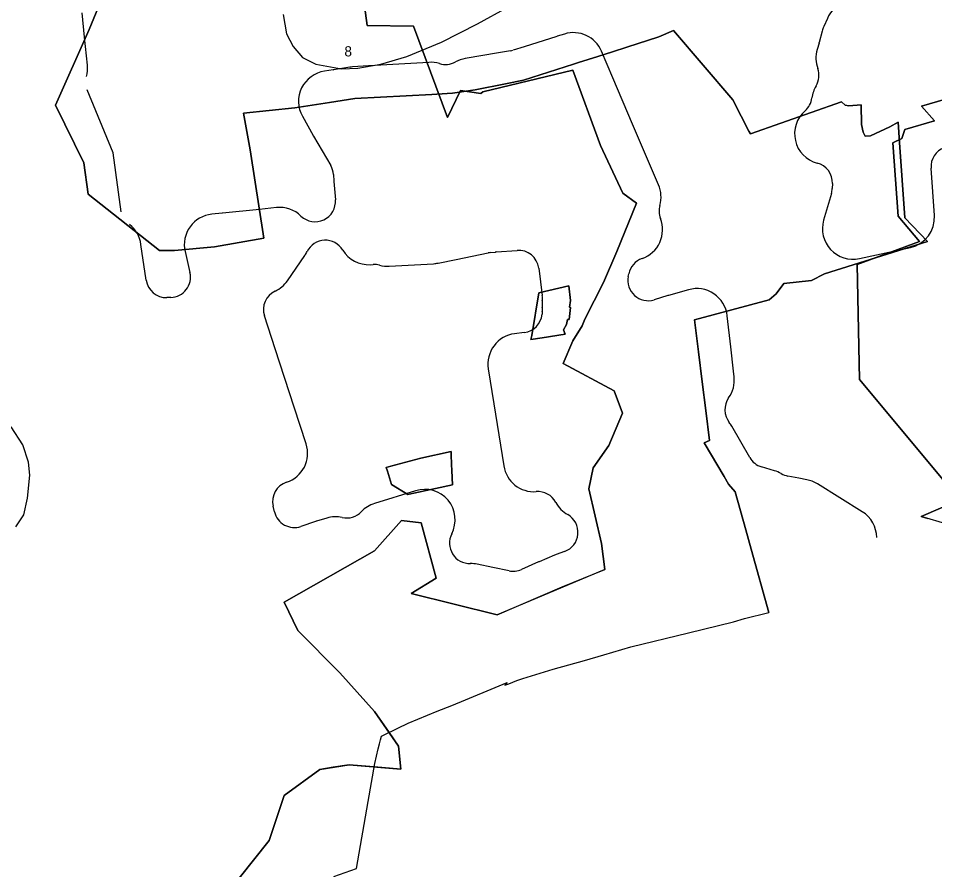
# Model space of a CAD drawing. Extents: x -445049 to -430649, y -1142304 to -1129816.
# Drawn here: x -443023 to -442122, y -1133134 to -1132297 of the extents above; entities that cross this region are included whole.
import ezdxf

# ---------------------------------------------------------------- set-up
doc = ezdxf.new("R2010")
doc.units = 0
for name, color, linetype in [('Vrstva 10', 7, 'Continuous'), ('Vrstva 23', 7, 'Continuous'), ('Vrstva 51', 7, 'Continuous'), ('Vrstva 7', 7, 'Continuous'), ('Vrstva 8', 7, 'Continuous'), ('Vrstva 9', 7, 'Continuous')]:
    doc.layers.add(name, color=color, linetype=linetype)

msp = doc.modelspace()

# ---------------------------------------------------------------- linework, layer by layer
at = {"layer": 'Vrstva 10'}
msp.add_lwpolyline([(-442109.03, -1132794.68), (-442135.55, -1132786.74), (-442097.52, -1132770.3), (-442196.18, -1132652.14), (-442198.38, -1132539.08), (-442137.12, -1132516.56), (-442158.19, -1132491.81), (-442163.27, -1132419.71), (-442154.54, -1132415.62), (-442151.59, -1132406.77), (-442122.25, -1132397.95), (-442135.23, -1132383.63), (-442097.99, -1132372.93)], dxfattribs=at)
at = {"layer": 'Vrstva 23'}
for p, q in [((-442957.74, -1132315.82), (-442960.18, -1132291.9)), ((-442227.66, -1132297.45), (-442231.2, -1132305.52)), ((-442232.75, -1132310.02), (-442235.63, -1132321.09)), ((-442954.94, -1132343.31), (-442957.74, -1132315.82)), ((-442493.43, -1132315.14), (-442525.56, -1132325.32)), ((-442486.1, -1132312.86), (-442493.26, -1132315.09)), ((-442235.8, -1132321.69), (-442237.68, -1132328.11)), ((-442539.18, -1132329.4), (-442550.89, -1132331.43)), ((-442525.63, -1132325.34), (-442536.62, -1132328.79)), ((-442438.41, -1132355.92), (-442449.62, -1132329.71)), ((-442551.01, -1132331.46), (-442583.52, -1132336.89)), ((-442713.29, -1132348.06), (-442721.83, -1132349.33)), ((-442696.97, -1132345.45), (-442713.06, -1132348.03)), ((-442678.78, -1132344.02), (-442694.4, -1132345.15)), ((-442619.3, -1132340.69), (-442678.28, -1132343.99)), ((-442419.09, -1132401.26), (-442438.4, -1132355.96)), ((-442743.65, -1132393.58), (-442733.12, -1132412.52)), ((-442393.54, -1132460.98), (-442419.08, -1132401.29)), ((-442732.79, -1132413.1), (-442715.81, -1132442.13)), ((-442122.5, -1132491.05), (-442125.76, -1132444.58)), ((-442713.13, -1132450.74), (-442712.63, -1132457.45)), ((-442712.62, -1132457.65), (-442711.15, -1132475.65)), ((-442222.69, -1132459.74), (-442222.89, -1132464.67)), ((-442223.67, -1132469.45), (-442231.32, -1132495.7)), ((-442768.9, -1132483.34), (-442785.65, -1132485.04)), ((-442822.34, -1132488.76), (-442832.71, -1132489.83)), ((-442785.65, -1132485.04), (-442822.28, -1132488.75)), ((-442897.11, -1132554.65), (-442902.23, -1132519.43)), ((-442858.87, -1132526.42), (-442854.12, -1132547)), ((-442592.49, -1132534.2), (-442560.97, -1132527.8)), ((-442559.04, -1132527.5), (-442553.72, -1132526.95)), ((-442553.15, -1132526.9), (-442532.68, -1132525.39)), ((-442196.12, -1132533.4), (-442146.02, -1132522.46)), ((-442758.36, -1132555.17), (-442741.27, -1132530.36)), ((-442741.27, -1132530.35), (-442741.17, -1132530.21)), ((-442610.33, -1132537.86), (-442592.53, -1132534.2)), ((-442676.81, -1132539.4), (-442674.08, -1132539.27)), ((-442658.19, -1132540.96), (-442614.62, -1132538.42)), ((-442511.38, -1132542.74), (-442507.85, -1132569.69)), ((-442423.3, -1132550.9), (-442422.8, -1132548.36)), ((-442364.18, -1132564.03), (-442383.92, -1132569.71)), ((-442872.96, -1132571.65), (-442876.71, -1132571.76)), ((-442384.3, -1132569.83), (-442397.89, -1132573.94)), ((-442770.36, -1132621.97), (-442780.93, -1132589.7)), ((-442507.87, -1132585.65), (-442508.11, -1132588.09)), ((-442322.63, -1132620.13), (-442326.06, -1132589.51)), ((-442525.49, -1132606.01), (-442535.04, -1132607.23)), ((-442751.63, -1132679.36), (-442770.35, -1132622)), ((-442319.97, -1132643.84), (-442322.63, -1132620.14)), ((-442560.87, -1132641.74), (-442555.38, -1132675.91)), ((-442319.32, -1132649.42), (-442319.96, -1132643.94)), ((-442739.92, -1132715.25), (-442751.62, -1132679.37)), ((-442555.37, -1132675.96), (-442550.51, -1132706.63)), ((-442304.03, -1132728.71), (-442321.53, -1132698.1)), ((-442550.51, -1132706.63), (-442545.69, -1132737.06)), ((-442279.61, -1132741.74), (-442292.35, -1132737.96)), ((-442255.77, -1132749.05), (-442266.65, -1132746.98)), ((-442247.76, -1132750.57), (-442255.77, -1132749.05)), ((-442632.38, -1132761.4), (-442672.71, -1132773.93)), ((-442193.37, -1132782.02), (-442237.52, -1132754.57)), ((-442771.06, -1132782.17), (-442772.36, -1132776.66)), ((-442719.65, -1132788.24), (-442729.71, -1132791.27)), ((-442730.73, -1132791.6), (-442745.14, -1132796.51)), ((-442495.73, -1132824.7), (-442511.06, -1132831.2)), ((-442485.94, -1132821.12), (-442494.19, -1132824.1)), ((-442556.5, -1132836.74), (-442571.71, -1132833.56)), ((-442511.41, -1132831.35), (-442528.41, -1132838.82)), ((-442540.54, -1132840.08), (-442556.5, -1132836.74))]:
    msp.add_line(p, q, dxfattribs=at)
msp.add_lwpolyline([(-442921.64, -1132487.44), (-442929.57, -1132429.68), (-442955.18, -1132367.68)], dxfattribs=at)
for centre, radius, start, end in [((-442200.18, -1132309.49), 30, 136.62933, 156.33647), ((-442477.2, -1132341.51), 30, 23.15168, 107.25965), ((-442203.72, -1132317.56), 30, 156.33647, 165.43444), ((-442937.84, -1132313.79), 20, 185.82227, 185.82544), ((-442484.36, -1132343.73), 30, 107.25965, 107.58988), ((-442254.99, -1132316.06), 20, 343.64627, 345.43444), ((-442542.6, -1132309.7), 20, 279.83922, 287.37641), ((-442531.6, -1132306.26), 20, 287.37641, 287.58988), ((-442208.89, -1132336.55), 30, 163.64627, 199.84662), ((-442578.57, -1132366.48), 30, 99.49232, 119.21234), ((-442554.31, -1132311.73), 20, 279.49232, 279.83922), ((-442984.78, -1132346.35), 30, 344.10309, 5.82544), ((-442716.22, -1132328.28), 20, 278.44397, 279.08948), ((-442692.23, -1132375.07), 30, 94.15381, 99.08948), ((-442676.61, -1132373.94), 30, 93.19748, 94.15381), ((-442617.62, -1132370.64), 30, 72.95959, 93.19748), ((-442602.97, -1132322.84), 20, 252.95959, 299.21234), ((-442255.92, -1132353.53), 20, 328.95738, 19.84662), ((-442717.43, -1132379), 30, 98.44397, 209.06864), ((-442466, -1132367.72), 30, 23.07993, 23.15168), ((-442212.78, -1132379.49), 30.35, 148.95738, 172.76176), ((-442262.73, -1132373.15), 20, 310.92226, 352.76176), ((-442230.13, -1132410.76), 29.77, 130.92226, 255.41229), ((-442400.69, -1132393.42), 20, 203.07993, 203.16557), ((-442706.9, -1132397.95), 30, 209.06864, 210.32596), ((-442105.81, -1132443.17), 20, 110.6205, 184.01796), ((-442191.84, -1132439.88), 50, 177.60823, 177.64508), ((-442733.08, -1132452.22), 20, 4.259, 30.32596), ((-442242.67, -1132458.92), 20, 357.64508, 75.41229), ((-442682.71, -1132455.22), 30, 184.25897, 184.65397), ((-442421.12, -1132472.78), 30, 343.82915, 23.16557), ((-442242.87, -1132463.85), 20, 343.74529, 357.64508), ((-442765.87, -1132513.19), 30, 45.9152, 95.7926), ((-442731.08, -1132477.27), 20, 225.9152, 4.65396), ((-442373.1, -1132486.71), 20, 163.82915, 201.5094), ((-442829.64, -1132519.67), 30, 95.88775, 192.9966), ((-442819.26, -1132518.6), 30, 95.78982, 95.88775), ((-442787.67, -1132465.14), 20, 275.78982, 275.7926), ((-442152.42, -1132493.15), 30, 282.32123, 4.01796), ((-442931.92, -1132523.75), 30, 8.27726, 52.36246), ((-442419.62, -1132505.04), 30, 289.19359, 21.5094), ((-442202.52, -1132504.09), 30, 163.74529, 282.32123), ((-442721.06, -1132535.36), 20, 31.22603, 153.67299), ((-442765.87, -1132513.19), 30, 325.43977, 333.67299), ((-442678.3, -1132509.44), 30, 211.22603, 272.84214), ((-442556.99, -1132547.4), 20, 95.88585, 101.47902), ((-442551.67, -1132546.85), 20, 94.23101, 95.88585), ((-442531.21, -1132545.33), 20, 7.46163, 94.23101), ((-442724.8, -1132541.7), 20, 145.43977, 145.44951), ((-442616.36, -1132508.47), 30, 273.3252, 281.61099), ((-442588.5, -1132553.8), 20, 101.47902, 101.61099), ((-442403.18, -1132552.26), 20, 109.19359, 168.76185), ((-442673.09, -1132559.24), 20, 74.74496, 92.84214), ((-442659.93, -1132511.01), 30, 254.74496, 273.3252), ((-442877.32, -1132551.77), 20, 188.27726, 271.74737), ((-442873.57, -1132551.66), 20, 271.74737, 13.18493), ((-442824.89, -1132540.25), 30, 192.9966, 193.18493), ((-442783.07, -1132538.16), 30, 295.00864, 325.44951), ((-442403.68, -1132554.8), 20, 168.76185, 286.83942), ((-442355.87, -1132592.85), 30, 6.39032, 106.07109), ((-442761.93, -1132583.47), 20, 115.00864, 198.13953), ((-442527.68, -1132572.29), 20, 353.04978, 7.46163), ((-442375.61, -1132598.54), 30, 106.07109, 106.83942), ((-442478.05, -1132578.34), 30, 173.04978, 186.09223), ((-442527.76, -1132583.64), 20, 354.25098, 6.09223), ((-442528.02, -1132586.17), 20, 277.27102, 354.34773), ((-442478.26, -1132591.09), 30, 174.25098, 174.34773), ((-442531.25, -1132636.98), 30, 97.27102, 189.13006), ((-442798.87, -1132631.31), 30, 18.08071, 18.13953), ((-442302.75, -1132617.91), 20, 186.39032, 186.3974), ((-442300.09, -1132641.61), 20, 186.3974, 186.6774), ((-442349.11, -1132652.91), 30, 324.52822, 6.6774), ((-442308.39, -1132681.93), 20, 144.52822, 218.41396), ((-442780.14, -1132688.67), 30, 18.05894, 18.08071), ((-442575.12, -1132679.08), 20, 8.99993, 9.13006), ((-442347.57, -1132712.99), 30, 29.76045, 38.41396), ((-442570.26, -1132709.76), 20, 8.99472, 8.99993), ((-442768.45, -1132724.55), 30, 288.12384, 18.05894), ((-442286.66, -1132718.79), 20, 209.75853, 253.49032), ((-442516.06, -1132732.37), 30, 188.99472, 274.36892), ((-442288.14, -1132770.5), 30, 59.69874, 73.49032), ((-442262.91, -1132727.33), 20, 239.69874, 259.22819), ((-442752.89, -1132772.07), 20, 108.12384, 193.25843), ((-442252.03, -1132729.4), 20, 259.22819, 259.2388), ((-442253.36, -1132780.04), 30, 58.12147, 79.2388), ((-442623.48, -1132790.05), 30, 332.75604, 107.25158), ((-442512.25, -1132782.22), 20, 27.9218, 94.36892), ((-442663.81, -1132802.58), 30, 107.25158, 136.50496), ((-442468.07, -1132758.81), 30, 207.9218, 240.46264), ((-442751.59, -1132777.58), 20, 193.25843, 288.82418), ((-442710.98, -1132816.96), 30, 77.4082, 106.78491), ((-442700.08, -1132768.16), 20, 257.4082, 316.50496), ((-442492.72, -1132802.31), 20, 289.82444, 60.46264), ((-442209.21, -1132807.5), 30, 0.15915, 58.12147), ((-442721.05, -1132820), 30, 106.78491, 108.82418), ((-442579.03, -1132812.94), 20, 152.75604, 271.35626), ((-442484.02, -1132852.32), 30, 109.82444, 112.97972), ((-442577.85, -1132862.93), 30, 78.18999, 91.35626), ((-442499.35, -1132858.82), 30, 112.97972, 113.70018), ((-442552.41, -1132817.17), 20, 258.18999, 258.19838), ((-442536.45, -1132820.5), 20, 258.19838, 293.70018)]:
    msp.add_arc(centre, radius, start, end, dxfattribs=at)
at = {"layer": 'Vrstva 51'}
for points in [[(-442762.66, -1132293.74), (-442759.13, -1132312.56), (-442752.64, -1132325), (-442743.57, -1132335.99), (-442730.45, -1132342.34), (-442705.24, -1132347.12), (-442689.1, -1132346.27), (-442666.56, -1132342.61), (-442640.85, -1132335.06), (-442606.79, -1132320.72), (-442571.63, -1132302.75), (-442541.55, -1132286.46)], [(-443025.22, -1132796.81), (-443017.38, -1132785.12), (-443013.68, -1132768.61), (-443011.59, -1132746.25), (-443012.68, -1132733.48), (-443018.34, -1132716.27), (-443029.71, -1132698.63)]]:
    msp.add_lwpolyline(points, dxfattribs=at)
at = {"layer": 'Vrstva 7'}
for points in [[(-442922.59, -1132233.93), (-442953.25, -1132308.47), (-442986.29, -1132382.77), (-442958.54, -1132439.22), (-442954.29, -1132470.17), (-442883.88, -1132525.49), (-442869.19, -1132525.36), (-442829.94, -1132521.75), (-442781.57, -1132513.28), (-442795.03, -1132426.67), (-442801.63, -1132390.42), (-442750.9, -1132385.4), (-442717.09, -1132380.1), (-442691.93, -1132376.15), (-442616.35, -1132372.16), (-442616.35, -1132372.16), (-442611.45, -1132371.9), (-442596.16, -1132371.1), (-442573.78, -1132367.82), (-442543.93, -1132361.77), (-442526.36, -1132358.21), (-442477.04, -1132342.43), (-442472.26, -1132340.9), (-442453.33, -1132334.85), (-442438.85, -1132330.22), (-442424.65, -1132325.68), (-442393.28, -1132315.65), (-442378.77, -1132309.31), (-442320.57, -1132377.44), (-442312.27, -1132393.66), (-442304.72, -1132408.4), (-442303.09, -1132411.01), (-442213.73, -1132379.55), (-442210.06, -1132382.66), (-442206.65, -1132383.46), (-442194.59, -1132382.53), (-442194.21, -1132401.61), (-442192.39, -1132409.19), (-442190.46, -1132413.21), (-442185.39, -1132412.76), (-442166.39, -1132404.06), (-442157.99, -1132399.36), (-442156.75, -1132419.42), (-442151.64, -1132493.29), (-442129.19, -1132516.78), (-442230.4, -1132548.48), (-442243.24, -1132554.95), (-442270.61, -1132557.94), (-442277.91, -1132567.95), (-442284.89, -1132573.96), (-442358.4, -1132593.69), (-442354.45, -1132625), (-442350.74, -1132654.35), (-442347.15, -1132682.73), (-442343.44, -1132712.19), (-442348.83, -1132714.24), (-442328.94, -1132747.55), (-442324.92, -1132754.94), (-442318.3, -1132762.38), (-442307.93, -1132799.8), (-442302.55, -1132818.91), (-442285.23, -1132881.09)], [(-442712.69, -1133140.21), (-442690.54, -1133132.6), (-442678.94, -1133066.74), (-442672.35, -1133029.29), (-442669.09, -1133015.08), (-442667.79, -1133010.13), (-442666.7, -1133005.99), (-442665.82, -1133002.63), (-442648.47, -1132994.02), (-442645.79, -1132992.69), (-442643.47, -1132991.54), (-442639.52, -1132989.58), (-442611.14, -1132977.99), (-442596.71, -1132972.33), (-442583.36, -1132966.7), (-442554.21, -1132954.62), (-442542.26, -1132949.89), (-442544.59, -1132952.4), (-442540.74, -1132951.01), (-442532.91, -1132947.79), (-442527.04, -1132945.99), (-442497.2, -1132936.83), (-442466.36, -1132928.28), (-442447.46, -1132922.71), (-442420.82, -1132914.86), (-442364.23, -1132900.95), (-442319.76, -1132890.16), (-442309.05, -1132886.83), (-442285.23, -1132881.09), (-442302.55, -1132818.91), (-442307.93, -1132799.8), (-442318.3, -1132762.38), (-442324.92, -1132754.94), (-442328.94, -1132747.55), (-442348.83, -1132714.24), (-442343.44, -1132712.19), (-442347.15, -1132682.73), (-442350.74, -1132654.35), (-442354.45, -1132625), (-442358.4, -1132593.69), (-442284.89, -1132573.96), (-442277.91, -1132567.95), (-442270.61, -1132557.94), (-442243.24, -1132554.95), (-442230.4, -1132548.48), (-442129.19, -1132516.78), (-442151.64, -1132493.29), (-442156.75, -1132419.42), (-442157.99, -1132399.36), (-442166.39, -1132404.06), (-442185.39, -1132412.76), (-442190.46, -1132413.21), (-442192.39, -1132409.19), (-442194.21, -1132401.61), (-442194.59, -1132382.53), (-442206.65, -1132383.46), (-442210.06, -1132382.66), (-442213.73, -1132379.55), (-442303.09, -1132411.01), (-442304.72, -1132408.4), (-442312.27, -1132393.66), (-442320.57, -1132377.44), (-442378.77, -1132309.31), (-442393.28, -1132315.65), (-442424.65, -1132325.68), (-442438.85, -1132330.22), (-442453.33, -1132334.85), (-442472.26, -1132340.9), (-442477.04, -1132342.43), (-442526.36, -1132358.21), (-442543.93, -1132361.77), (-442573.78, -1132367.82), (-442596.16, -1132371.1), (-442611.45, -1132371.9), (-442616.35, -1132372.16), (-442691.93, -1132376.15), (-442717.09, -1132380.1), (-442750.9, -1132385.4), (-442801.63, -1132390.42), (-442795.03, -1132426.67), (-442781.57, -1132513.28), (-442829.94, -1132521.75), (-442869.19, -1132525.36), (-442883.88, -1132525.49), (-442954.29, -1132470.17), (-442958.54, -1132439.22), (-442986.29, -1132382.77), (-442953.25, -1132308.47), (-442922.59, -1132233.93)], [(-442712.69, -1133140.21), (-442690.54, -1133132.6), (-442678.94, -1133066.74), (-442672.35, -1133029.29), (-442669.09, -1133015.08), (-442667.79, -1133010.13), (-442666.7, -1133005.99), (-442665.82, -1133002.63), (-442648.47, -1132994.02), (-442645.79, -1132992.69), (-442643.47, -1132991.54), (-442639.52, -1132989.58), (-442611.14, -1132977.99), (-442596.71, -1132972.33), (-442583.36, -1132966.7), (-442554.21, -1132954.62), (-442542.26, -1132949.89), (-442544.59, -1132952.4), (-442540.74, -1132951.01), (-442532.91, -1132947.79), (-442527.04, -1132945.99), (-442497.2, -1132936.83), (-442466.36, -1132928.28), (-442447.46, -1132922.71), (-442420.82, -1132914.86), (-442364.23, -1132900.95), (-442319.76, -1132890.16), (-442309.05, -1132886.83), (-442285.23, -1132881.09), (-442302.55, -1132818.91), (-442307.93, -1132799.8), (-442318.3, -1132762.38), (-442324.92, -1132754.94), (-442328.94, -1132747.55), (-442348.83, -1132714.24), (-442343.44, -1132712.19), (-442347.15, -1132682.73), (-442350.74, -1132654.35), (-442354.45, -1132625), (-442358.4, -1132593.69), (-442284.89, -1132573.96), (-442277.91, -1132567.95), (-442270.61, -1132557.94), (-442243.24, -1132554.95), (-442230.4, -1132548.48), (-442129.19, -1132516.78), (-442151.64, -1132493.29), (-442156.75, -1132419.42), (-442157.99, -1132399.36), (-442166.39, -1132404.06), (-442185.39, -1132412.76), (-442190.46, -1132413.21), (-442192.39, -1132409.19), (-442194.21, -1132401.61), (-442194.59, -1132382.53), (-442206.65, -1132383.46), (-442210.06, -1132382.66), (-442213.73, -1132379.55), (-442303.09, -1132411.01), (-442304.72, -1132408.4), (-442312.27, -1132393.66), (-442320.57, -1132377.44), (-442378.77, -1132309.31), (-442393.28, -1132315.65), (-442424.65, -1132325.68), (-442438.85, -1132330.22), (-442453.33, -1132334.85), (-442472.26, -1132340.9), (-442477.04, -1132342.43), (-442526.36, -1132358.21), (-442543.93, -1132361.77), (-442573.78, -1132367.82), (-442596.16, -1132371.1), (-442611.45, -1132371.9), (-442616.35, -1132372.16), (-442691.93, -1132376.15), (-442717.09, -1132380.1), (-442750.9, -1132385.4), (-442801.63, -1132390.42), (-442795.03, -1132426.67), (-442781.57, -1132513.28), (-442829.94, -1132521.75), (-442869.19, -1132525.36), (-442883.88, -1132525.49), (-442954.29, -1132470.17), (-442958.54, -1132439.22), (-442986.29, -1132382.77), (-442953.25, -1132308.47), (-442922.59, -1132233.93)], [(-442481.77, -1132560.24), (-442480.15, -1132574.46), (-442481.23, -1132581.27), (-442480.06, -1132581.44), (-442481.54, -1132593.18), (-442483.12, -1132593.13), (-442483.91, -1132598.1), (-442486.83, -1132603.3), (-442485.38, -1132607.73), (-442507.9, -1132611.25), (-442519.13, -1132613.01), (-442518.26, -1132609.08), (-442511.21, -1132567.18), (-442481.77, -1132560.24)], [(-442597.5, -1132722.99), (-442597.37, -1132725.74), (-442596.92, -1132735.58), (-442596.65, -1132741.41), (-442596, -1132755.59), (-442634.02, -1132763.9), (-442640.09, -1132765.23), (-442655.95, -1132755.3), (-442660.01, -1132742.11), (-442661.14, -1132738.48), (-442656.8, -1132737.33), (-442627.12, -1132729.44), (-442597.5, -1132722.99)]]:
    msp.add_lwpolyline(points, dxfattribs=at)
for points in [[(-442481.77, -1132560.24), (-442511.21, -1132567.18), (-442518.26, -1132609.08), (-442519.13, -1132613.01), (-442507.9, -1132611.25), (-442485.38, -1132607.73), (-442486.83, -1132603.3), (-442483.91, -1132598.1), (-442483.12, -1132593.13), (-442481.54, -1132593.18), (-442480.06, -1132581.44), (-442481.23, -1132581.27), (-442480.15, -1132574.46)], [(-442597.5, -1132722.99), (-442627.12, -1132729.44), (-442656.8, -1132737.33), (-442661.14, -1132738.48), (-442660.01, -1132742.11), (-442655.95, -1132755.3), (-442640.09, -1132765.23), (-442634.02, -1132763.9), (-442596, -1132755.59), (-442596.65, -1132741.41), (-442596.92, -1132735.58), (-442597.37, -1132725.74)]]:
    msp.add_lwpolyline(points, close=True, dxfattribs=at)
at = {"layer": 'Vrstva 8'}
for points in [[(-442686.56, -1132255.99), (-442680.09, -1132304.51), (-442634.44, -1132305.05), (-442600.88, -1132394.78), (-442588.34, -1132368.36), (-442568.38, -1132371.16), (-442566.42, -1132369.58), (-442477.76, -1132348.51), (-442450.55, -1132422.25), (-442428.65, -1132469.3), (-442415.39, -1132479.09), (-442434.45, -1132526.47), (-442447.62, -1132557.04), (-442465.98, -1132592.97), (-442468.52, -1132599.61), (-442477.97, -1132614.28), (-442487.31, -1132636.43), (-442437.16, -1132663.37), (-442428.9, -1132685.25), (-442442.48, -1132717.15), (-442457.98, -1132738.95), (-442462.06, -1132759.7), (-442449.79, -1132813.19), (-442446.31, -1132838.66), (-442552.14, -1132883.33), (-442636.56, -1132862.44), (-442612.09, -1132847.34), (-442626.96, -1132793.03), (-442646.29, -1132790.53), (-442672.85, -1132820.57), (-442761.57, -1132870.8), (-442748.21, -1132898.79), (-442706.65, -1132940.19), (-442672.59, -1132978.12), (-442658.25, -1132998.9)], [(-442658.25, -1132998.9), (-442649.08, -1133012.18), (-442646.72, -1133034.99), (-442672.95, -1133032.71)], [(-442672.95, -1133032.71), (-442697.66, -1133030.53), (-442713.26, -1133033.01), (-442726.59, -1133035.13), (-442761.52, -1133060.83), (-442776.12, -1133104.83), (-442805.7, -1133141.9), (-442836.23, -1133168.46), (-442848.81, -1133188.3), (-442862.95, -1133235.36), (-442888.56, -1133275.04), (-442931.25, -1133319.68), (-442936.73, -1133333.97)]]:
    msp.add_lwpolyline(points, dxfattribs=at)
at = {"layer": 'Vrstva 9'}
for points in [[(-442805.7, -1133141.9), (-442776.12, -1133104.83), (-442761.52, -1133060.83), (-442726.59, -1133035.13), (-442697.66, -1133030.53), (-442646.72, -1133034.99), (-442649.08, -1133012.18), (-442672.59, -1132978.12), (-442706.65, -1132940.19), (-442748.21, -1132898.79), (-442761.57, -1132870.8), (-442672.85, -1132820.57), (-442646.29, -1132790.53), (-442626.96, -1132793.03), (-442612.09, -1132847.34), (-442636.56, -1132862.44), (-442552.14, -1132883.33), (-442488.27, -1132855.66), (-442446.31, -1132838.66), (-442449.79, -1132813.19), (-442462.06, -1132759.7), (-442457.98, -1132738.95), (-442442.48, -1132717.15), (-442428.9, -1132685.25), (-442437.16, -1132663.37), (-442487.31, -1132636.43), (-442477.97, -1132614.28), (-442468.52, -1132599.61), (-442465.98, -1132592.97), (-442447.62, -1132557.04), (-442434.45, -1132526.47), (-442415.39, -1132479.09), (-442428.65, -1132469.3), (-442450.55, -1132422.25), (-442477.76, -1132348.51), (-442566.42, -1132369.58), (-442568.38, -1132371.16), (-442588.34, -1132368.36), (-442600.88, -1132394.78), (-442634.44, -1132305.05), (-442680.09, -1132304.51), (-442686.56, -1132255.99)], [(-442097.99, -1132372.93), (-442135.23, -1132383.63), (-442122.25, -1132397.95), (-442151.59, -1132406.77), (-442154.54, -1132415.62), (-442163.27, -1132419.71), (-442158.19, -1132491.81), (-442137.12, -1132516.56), (-442198.38, -1132539.08), (-442196.18, -1132652.14), (-442097.52, -1132770.3), (-442135.55, -1132786.74), (-442128.79, -1132788.76)]]:
    msp.add_lwpolyline(points, dxfattribs=at)

# ---------------------------------------------------------------- texts
at = {"layer": 'Vrstva 51'}
msp.add_text('8', height=10, dxfattribs=at).set_placement((-442702.31, -1132334.84))

doc.saveas('drawing.dxf')
